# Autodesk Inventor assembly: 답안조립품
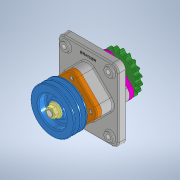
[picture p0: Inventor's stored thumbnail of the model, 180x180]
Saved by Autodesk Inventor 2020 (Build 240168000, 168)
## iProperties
Created: 2021-07
Part Number: 답안조립품
Document SubType Name: Assembly
Designer: Owner
Author: Owner
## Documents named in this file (16)
- C:\Users\Owner\Desktop\710707V1018\710707V1018\답안조립품.iam
- C:\Users\Owner\Desktop\710707V1018\710707V1018\본체.ipt
- C:\Users\Owner\Desktop\710707V1018\710707V1018\M16 너트.ipt
- C:\Users\Owner\Desktop\710707V1018\710707V1018\V-벨트풀리.ipt
- C:\Users\Owner\Desktop\710707V1018\710707V1018\멈춤나사 M4.ipt
- C:\Users\Owner\Desktop\710707V1018\710707V1018\베어링 6206.ipt
- C:\Users\Owner\Desktop\710707V1018\710707V1018\볼트 M6.ipt
- C:\Users\Owner\Desktop\710707V1018\710707V1018\오일실 30x42x8.ipt
- C:\Users\Owner\Desktop\710707V1018\710707V1018\오일실 30x45x8.ipt
- C:\Users\Owner\Desktop\710707V1018\710707V1018\체인 스프로킷.ipt
- C:\Users\Owner\Desktop\710707V1018\710707V1018\축.ipt
- C:\Users\Owner\Desktop\710707V1018\710707V1018\커버A.ipt
- C:\Users\Owner\Desktop\710707V1018\710707V1018\커버B.ipt
- C:\Users\Owner\Desktop\710707V1018\710707V1018\키 6x6x18.ipt
- C:\Users\Owner\Desktop\710707V1018\710707V1018\키 6x6x20.ipt
- C:\Users\Owner\Desktop\710707V1018\710707V1018\부시.ipt
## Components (3 placed, 2 different names)
1. M16 너트:1 — 각도:3
2. V-벨트풀리:1 — 각도:2
3. M16 너트:2 — 각도:4
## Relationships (3: Angle 3)
- 각도:2 [Angle]: V-벨트풀리:1
- 각도:3 [Angle]: M16 너트:1
- 각도:4 [Angle]: M16 너트:2
